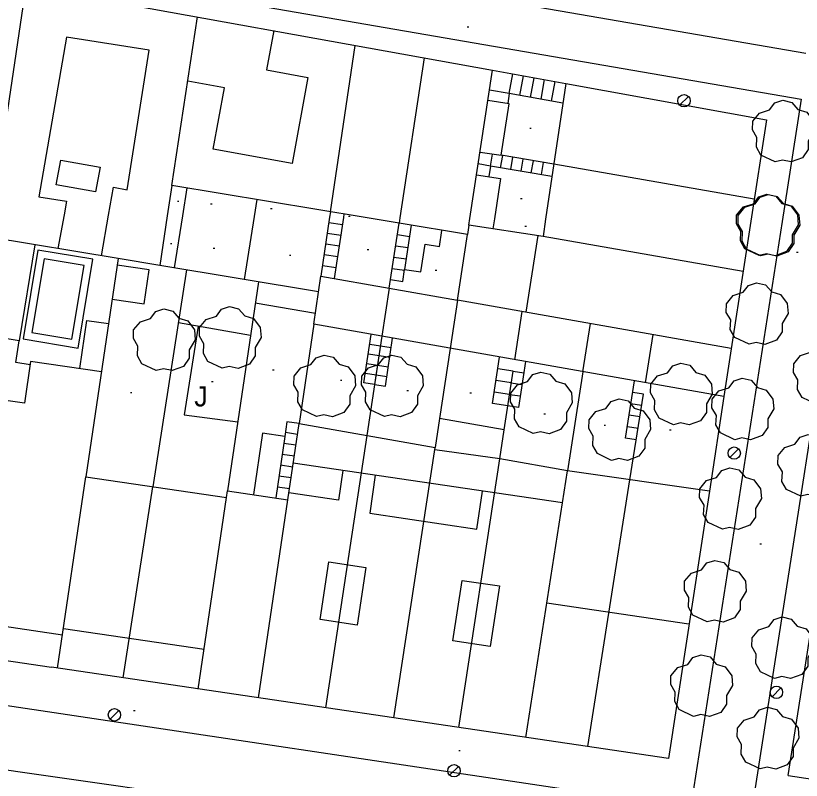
# Model space of a CAD drawing. Extents: x 431390 to 432653, y 4586754 to 4589600.
# Drawn here: x 431987.9 to 432038.9, y 4587146 to 4587195.6 of the extents above; entities that cross this region are included whole.
import ezdxf

# ---------------------------------------------------------------- set-up
doc = ezdxf.new("R2010")
doc.units = 0
for name, color, linetype in [('COM_17LS_LN', 7, 'Continuous'), ('CON_01_LN', 7, 'Continuous'), ('CON_01FI_LN', 7, 'Continuous'), ('CON_03_LN', 7, 'Continuous'), ('CON_04_LN', 7, 'Continuous'), ('CON_07_LN', 7, 'Continuous'), ('CON_14LN_LN', 7, 'Continuous'), ('CON_16_LN', 7, 'Continuous'), ('CON_23_LN', 7, 'Continuous'), ('CON_29_LN', 7, 'Continuous'), ('ENE_06_PT', 7, 'Continuous'), ('HID_11EX_LN', 7, 'Continuous'), ('HID_11IN_LN', 7, 'Continuous'), ('ORO_03_PT', 7, 'Continuous'), ('TOP_15JA_TX', 7, 'Continuous'), ('VEG_03_PT', 7, 'Continuous'), ('VEG_06_LN', 7, 'Continuous')]:
    doc.layers.add(name, color=color, linetype=linetype)

msp = doc.modelspace()

# ---------------------------------------------------------------- linework, layer by layer
at = {"layer": 'COM_17LS_LN'}
for points in [[(431987.522, 4587199.068), (432038.841, 4587190.205), (432037.603, 4587182.271), (432031.666, 4587144.248), (431980.566, 4587151.892), (431980.618, 4587152.238), (431953.282, 4587155.989), (431897.468, 4587164.433), (431900.621, 4587183.589), (431910.828, 4587250.379), (431908.915, 4587250.666), (431906.855, 4587250.975), (431896.747, 4587183.627), (431893.612, 4587165.02)], [(431987.959, 4587202.036), (432039.151, 4587193.195)], [(432035.594, 4587143.752), (432042.668, 4587189.061), (432055.977, 4587186.82)], [(432023.522, 4587088.838), (432031.211, 4587140.361), (432028.644, 4587140.733), (432001.332, 4587144.681), (431988.658, 4587146.513), (431982.216, 4587147.444)]]:
    msp.add_lwpolyline(points, dxfattribs=at)
at = {"layer": 'CON_01_LN'}
for points in [[(431984.788, 4587172.063), (431986.384, 4587182.764), (431988.59, 4587197.55), (432018.832, 4587192.088)], [(432023.578, 4587191.23), (432036.59, 4587188.88), (432035.578, 4587182.291), (432033.833, 4587170.926)], [(432037.99, 4587146.36), (432043.623, 4587182.213), (432044.477, 4587187.648)], [(431984.788, 4587172.063), (431982.178, 4587154.562), (431990.23, 4587153.37)], [(432032.892, 4587164.796), (432030.23, 4587147.46), (431990.23, 4587153.37)], [(432037.99, 4587146.36), (432045.032, 4587145.303)]]:
    msp.add_lwpolyline(points, dxfattribs=at)
at = {"layer": 'CON_01FI_LN'}
for points in [[(432023.578, 4587191.23), (432022.271, 4587182.419), (432022.107, 4587181.314), (432017.299, 4587182.029), (432017.366, 4587182.466), (432018.832, 4587192.088)], [(432033.833, 4587170.926), (432007.242, 4587175.611), (432007.704, 4587178.741), (432016.56, 4587177.18), (432017.208, 4587181.427), (432012.772, 4587182.165), (432010.565, 4587182.531), (431998.038, 4587184.614), (431997.741, 4587182.655), (431997.25, 4587179.422), (431994.546, 4587179.87), (431992.459, 4587165.716), (432001.581, 4587164.371), (432001.647, 4587164.817), (432005.562, 4587164.24), (432006.291, 4587169.175), (432015.104, 4587167.623)], [(432032.892, 4587164.796), (432023.685, 4587166.112), (432019.294, 4587166.885), (432019.58, 4587168.768), (432015.391, 4587169.505), (432015.104, 4587167.623)]]:
    msp.add_lwpolyline(points, dxfattribs=at)
at = {"layer": 'CON_03_LN'}
for points in [[(431998.038, 4587184.614), (431999.696, 4587195.544)], [(432008.319, 4587182.904), (432009.914, 4587193.699)], [(432014.398, 4587192.889), (432012.824, 4587182.51), (432012.772, 4587182.165)], [(432035.797, 4587183.715), (432022.801, 4587185.993)], [(432017.299, 4587182.029), (432017.208, 4587181.427)], [(431994.546, 4587179.87), (431986.159, 4587181.258)], [(432035.078, 4587179.037), (432022.107, 4587181.314)], [(432012.134, 4587177.96), (432011.659, 4587174.833)], [(432034.313, 4587174.05), (432016.56, 4587177.18), (432016.084, 4587174.053)], [(432020.272, 4587173.315), (432020.748, 4587176.442)], [(432024.687, 4587172.537), (432025.174, 4587175.661)], [(432029.222, 4587174.948), (432028.73, 4587171.825)], [(432010.684, 4587168.401), (432008.006, 4587150.744)], [(432012.433, 4587150.09), (432015.104, 4587167.623)], [(432020.99, 4587148.825), (432023.685, 4587166.112)], [(431990.629, 4587153.311), (431992.459, 4587165.716)], [(432025.01, 4587148.231), (432027.738, 4587165.533)], [(431999.747, 4587151.964), (432001.581, 4587164.371)], [(432003.662, 4587151.385), (432005.562, 4587164.24)]]:
    msp.add_lwpolyline(points, dxfattribs=at)
at = {"layer": 'CON_04_LN'}
for points in [[(432004.638, 4587194.652), (432004.178, 4587192.106), (432006.845, 4587191.624), (432005.835, 4587186.034), (432000.72, 4587186.958), (432001.44, 4587190.946), (431999.064, 4587191.375)], [(431993.465, 4587180.049), (431993.931, 4587182.692), (431994.25, 4587184.5), (431995.13, 4587184.34), (431996.56, 4587193.38), (431991.2, 4587194.24), (431989.41, 4587183.87), (431991.2, 4587183.59), (431991.041, 4587182.719), (431990.64, 4587180.517)], [(431990.83, 4587186.26), (431993.382, 4587185.8), (431993.093, 4587184.197), (431990.541, 4587184.657), (431990.83, 4587186.26)], [(432021.761, 4587181.365), (432020.981, 4587176.401)], [(431989.155, 4587180.762), (431988.126, 4587174.546), (431985.23, 4587175.025)], [(431992.068, 4587172.737), (431992.529, 4587175.861), (431993.925, 4587175.655)], [(431988.847, 4587172.989), (431987.917, 4587173.126), (431988.126, 4587174.546)], [(431993.464, 4587172.531), (431988.879, 4587173.207), (431988.478, 4587170.488), (431986.799, 4587170.736), (431984.686, 4587156.406), (431990.949, 4587155.482)], [(432019.294, 4587166.885), (432015.08, 4587167.465)], [(432016.643, 4587149.467), (432019.294, 4587166.885)], [(432023.361, 4587164.032), (432005.912, 4587166.61)], [(432009.129, 4587166.135), (432008.844, 4587164.204), (432005.627, 4587164.679)], [(432011.227, 4587165.825), (432010.863, 4587163.362), (432017.804, 4587162.337), (432018.168, 4587164.799)], [(431994.888, 4587152.682), (431996.812, 4587165.074)], [(432010.052, 4587156.113), (432007.644, 4587156.479), (432008.21, 4587160.214), (432010.619, 4587159.849), (432010.052, 4587156.113)], [(432018.675, 4587154.729), (432016.264, 4587155.096), (432016.86, 4587159.01), (432019.271, 4587158.643), (432018.675, 4587154.729)], [(432000.124, 4587154.516), (431991.005, 4587155.861)]]:
    msp.add_lwpolyline(points, dxfattribs=at)
at = {"layer": 'CON_07_LN'}
for points in [[(432018.022, 4587186.771), (432019.398, 4587186.568), (432019.907, 4587189.911), (432018.532, 4587190.121)], [(432017.799, 4587185.311), (432019.353, 4587185.074), (432018.954, 4587182.451), (432018.854, 4587181.798)], [(432013.561, 4587182.034), (432013.125, 4587179.165), (432014.18, 4587179.005), (432014.452, 4587180.802), (432015.388, 4587180.66), (432015.546, 4587181.703)], [(431994.159, 4587177.246), (431996.232, 4587176.94), (431996.557, 4587179.141), (431994.484, 4587179.447)], [(432003.447, 4587176.999), (432007.35, 4587176.344)], [(431998.465, 4587175.718), (432003.138, 4587174.91)], [(432005.36, 4587168.343), (432003.919, 4587168.556), (432003.33, 4587164.569)], [(432005.36, 4587168.343), (432004.771, 4587164.357)]]:
    msp.add_lwpolyline(points, dxfattribs=at)
at = {"layer": 'CON_14LN_LN'}
for points in [[(432007.553, 4587177.717), (431997.25, 4587179.422)], [(432003.648, 4587178.363), (432001.647, 4587164.817)]]:
    msp.add_lwpolyline(points, dxfattribs=at)
at = {"layer": 'CON_16_LN'}
for points in [[(432018.832, 4587192.088), (432023.578, 4587191.23)], [(431998.209, 4587179.263), (431998.741, 4587182.645), (431999.025, 4587184.45)], [(432003.551, 4587183.697), (432003.378, 4587182.601), (432002.734, 4587178.514)], [(432008.319, 4587182.904), (432008.267, 4587182.554), (432007.704, 4587178.741)], [(432012.134, 4587177.96), (432012.772, 4587182.165)], [(431998.995, 4587179.133), (431996.812, 4587165.074)], [(432007.242, 4587175.611), (432006.291, 4587169.175)], [(432011.659, 4587174.833), (432010.684, 4587168.401)], [(432016.084, 4587174.053), (432015.391, 4587169.505)], [(432019.58, 4587168.768), (432020.158, 4587172.566)], [(432024.687, 4587172.537), (432023.685, 4587166.112)], [(432027.738, 4587165.533), (432028.613, 4587171.084)], [(432033.833, 4587170.926), (432032.892, 4587164.796)]]:
    msp.add_lwpolyline(points, dxfattribs=at)
at = {"layer": 'CON_23_LN'}
for points in [[(432019.916, 4587190.571), (432020.147, 4587191.85)], [(432020.602, 4587190.447), (432020.833, 4587191.726)], [(432021.288, 4587190.323), (432021.519, 4587191.602)], [(432021.974, 4587190.199), (432022.205, 4587191.478)], [(432022.66, 4587190.075), (432022.891, 4587191.354)], [(432019.916, 4587190.571), (432018.636, 4587190.802)], [(432019.916, 4587190.571), (432019.817, 4587189.925)], [(432023.387, 4587189.944), (432019.916, 4587190.571)], [(432018.694, 4587185.875), (432018.825, 4587186.653)], [(432019.356, 4587185.763), (432019.489, 4587186.552)], [(432022.801, 4587185.993), (432019.38, 4587186.571)], [(432020.018, 4587185.651), (432020.152, 4587186.44)], [(432020.681, 4587185.539), (432020.814, 4587186.329)], [(432021.343, 4587185.428), (432021.476, 4587186.217)], [(432018.694, 4587185.875), (432017.906, 4587186.008)], [(432018.694, 4587185.875), (432018.579, 4587185.192)], [(432022.684, 4587185.201), (432018.694, 4587185.875)], [(432022.005, 4587185.316), (432022.138, 4587186.105)], [(432008.59, 4587178.585), (432009.176, 4587182.545), (432009.207, 4587182.757)], [(432008.216, 4587182.211), (432009.107, 4587182.08)], [(432008.114, 4587181.517), (432009.004, 4587181.386)], [(432012.661, 4587181.434), (432013.452, 4587181.314)], [(432008.011, 4587180.823), (432008.902, 4587180.692)], [(432012.55, 4587180.703), (432013.341, 4587180.583)], [(432007.909, 4587180.129), (432008.799, 4587179.998)], [(432012.439, 4587179.971), (432013.229, 4587179.851)], [(432007.806, 4587179.435), (432008.696, 4587179.304)], [(432012.217, 4587178.509), (432013.008, 4587178.389), (432013.126, 4587179.165)], [(432012.328, 4587179.24), (432013.119, 4587179.12)], [(432011.186, 4587171.715), (432010.494, 4587171.82), (432010.969, 4587174.954)], [(432011.659, 4587174.833), (432011.186, 4587171.715)], [(432011.186, 4587171.715), (432011.878, 4587171.61), (432012.348, 4587174.711)], [(432010.872, 4587174.314), (432011.564, 4587174.209), (432012.256, 4587174.104)], [(432010.778, 4587173.691), (432011.47, 4587173.586), (432012.162, 4587173.481)], [(432020.962, 4587173.194), (432020.508, 4587170.214), (432019.816, 4587170.319), (432018.827, 4587170.469), (432019.287, 4587173.489)], [(432010.683, 4587173.067), (432011.375, 4587172.962), (432012.067, 4587172.857)], [(432010.589, 4587172.444), (432011.281, 4587172.339), (432011.973, 4587172.234)], [(432020.158, 4587172.566), (432019.169, 4587172.716)], [(432020.158, 4587172.566), (432020.85, 4587172.461)], [(432020.044, 4587171.817), (432019.055, 4587171.967)], [(432028.146, 4587168.121), (432027.455, 4587168.23), (432028.041, 4587171.946)], [(432020.044, 4587171.817), (432020.736, 4587171.712)], [(432019.93, 4587171.068), (432018.941, 4587171.218)], [(432019.93, 4587171.068), (432020.622, 4587170.963)], [(432028.613, 4587171.084), (432027.922, 4587171.193)], [(432028.496, 4587170.343), (432027.805, 4587170.452)], [(432028.38, 4587169.603), (432027.689, 4587169.712)], [(432006.291, 4587169.175), (432005.5, 4587169.292), (432005.36, 4587168.343)], [(432028.263, 4587168.862), (432027.572, 4587168.971)], [(432006.187, 4587168.47), (432005.396, 4587168.587)], [(432006.083, 4587167.765), (432005.292, 4587167.882)], [(432005.979, 4587167.06), (432005.188, 4587167.177)], [(432005.874, 4587166.355), (432005.084, 4587166.472)], [(432005.77, 4587165.65), (432004.979, 4587165.767)], [(432005.666, 4587164.945), (432004.875, 4587165.062)]]:
    msp.add_lwpolyline(points, dxfattribs=at)
at = {"layer": 'CON_29_LN'}
msp.add_lwpolyline([(432031.566, 4587156.163), (432022.347, 4587157.532)], dxfattribs=at)
at = {"layer": 'ENE_06_PT'}
for p, q in [((432031.529, 4587190.393), (432030.963, 4587189.827)), ((432034.782, 4587167.542), (432034.216, 4587166.976)), ((432037.522, 4587152.032), (432036.956, 4587151.466)), ((431994.592, 4587150.572), (431994.026, 4587150.006)), ((432016.614, 4587146.943), (432016.048, 4587146.377))]:
    msp.add_line(p, q, dxfattribs=at)
for centre in [(432031.246, 4587190.11), (432034.499, 4587167.259), (432037.239, 4587151.749), (431994.309, 4587150.289), (432016.331, 4587146.66)]:
    msp.add_circle(centre, 0.4, dxfattribs=at)
at = {"layer": 'HID_11EX_LN'}
msp.add_lwpolyline([(431988.385, 4587174.662), (431991.963, 4587174.069), (431992.917, 4587179.836), (431989.339, 4587180.428), (431988.385, 4587174.662)], dxfattribs=at)
at = {"layer": 'HID_11IN_LN'}
msp.add_lwpolyline([(431988.96, 4587175.073), (431991.551, 4587174.644), (431992.342, 4587179.424), (431989.751, 4587179.853), (431988.96, 4587175.073)], dxfattribs=at)
at = {"layer": 'ORO_03_PT'}
for p, q in [((432017.183, 4587194.905), (432017.283, 4587194.905)), ((432021.24, 4587188.34), (432021.34, 4587188.34)), ((431998.39, 4587183.59), (431998.49, 4587183.59)), ((432020.65, 4587183.77), (432020.75, 4587183.77)), ((432000.54, 4587183.43), (432000.64, 4587183.43)), ((432004.43, 4587183.11), (432004.53, 4587183.11)), ((432009.5, 4587182.62), (432009.6, 4587182.62)), ((432020.93, 4587181.97), (432021.03, 4587181.97)), ((431997.94, 4587180.85), (431998.04, 4587180.85)), ((432000.72, 4587180.54), (432000.82, 4587180.54)), ((432005.66, 4587180.1), (432005.76, 4587180.1)), ((432010.71, 4587180.47), (432010.81, 4587180.47)), ((432038.55, 4587180.29), (432038.65, 4587180.29)), ((432015.12, 4587179.13), (432015.22, 4587179.13)), ((432004.56, 4587172.66), (432004.66, 4587172.66)), ((432000.61, 4587171.91), (432000.71, 4587171.91)), ((432008.96, 4587172), (432009.06, 4587172)), ((431995.35, 4587171.18), (431995.45, 4587171.18)), ((432013.28, 4587171.32), (432013.38, 4587171.32)), ((432017.36, 4587171.17), (432017.46, 4587171.17)), ((432022.16, 4587169.8), (432022.26, 4587169.8)), ((432026.06, 4587169.07), (432026.16, 4587169.07)), ((432030.31, 4587168.77), (432030.41, 4587168.77)), ((432036.173, 4587161.387), (432036.273, 4587161.387)), ((431995.55, 4587150.57), (431995.65, 4587150.57)), ((432016.64, 4587147.98), (432016.74, 4587147.98))]:
    msp.add_line(p, q, dxfattribs=at)
at = {"layer": 'VEG_03_PT'}
for points in [[(432037.164, 4587186.151), (432036.237, 4587186.586), (432035.949, 4587187.107), (432035.972, 4587187.721), (432035.69, 4587188.213), (432035.698, 4587188.776), (432036.139, 4587189.311), (432036.792, 4587189.515), (432037.127, 4587189.966), (432037.653, 4587190.136), (432038.233, 4587190.003), (432038.633, 4587189.537), (432039.207, 4587189.367), (432039.641, 4587188.784), (432039.69, 4587188.142), (432039.307, 4587187.495), (432039.307, 4587186.945), (432038.935, 4587186.411), (432038.196, 4587186.136), (432037.631, 4587186.264), (432037.164, 4587186.151)], [(432036.125, 4587180.068), (432035.198, 4587180.503), (432034.91, 4587181.024), (432034.933, 4587181.638), (432034.651, 4587182.13), (432034.659, 4587182.693), (432035.1, 4587183.228), (432035.753, 4587183.432), (432036.088, 4587183.883), (432036.614, 4587184.053), (432037.194, 4587183.92), (432037.594, 4587183.454), (432038.168, 4587183.284), (432038.602, 4587182.701), (432038.651, 4587182.059), (432038.268, 4587181.412), (432038.268, 4587180.862), (432037.896, 4587180.328), (432037.157, 4587180.053), (432036.592, 4587180.181), (432036.125, 4587180.068)], [(432036.224, 4587180.051), (432035.297, 4587180.486), (432035.009, 4587181.007), (432035.032, 4587181.621), (432034.75, 4587182.113), (432034.758, 4587182.676), (432035.199, 4587183.211), (432035.852, 4587183.415), (432036.187, 4587183.866), (432036.713, 4587184.036), (432037.293, 4587183.903), (432037.693, 4587183.437), (432038.267, 4587183.267), (432038.701, 4587182.684), (432038.75, 4587182.042), (432038.367, 4587181.395), (432038.367, 4587180.845), (432037.995, 4587180.311), (432037.256, 4587180.036), (432036.691, 4587180.164), (432036.224, 4587180.051)], [(432035.464, 4587174.321), (432034.537, 4587174.756), (432034.249, 4587175.277), (432034.272, 4587175.891), (432033.99, 4587176.383), (432033.998, 4587176.946), (432034.439, 4587177.481), (432035.092, 4587177.685), (432035.427, 4587178.136), (432035.953, 4587178.306), (432036.533, 4587178.173), (432036.933, 4587177.707), (432037.507, 4587177.537), (432037.941, 4587176.954), (432037.99, 4587176.312), (432037.607, 4587175.665), (432037.607, 4587175.115), (432037.235, 4587174.581), (432036.496, 4587174.306), (432035.931, 4587174.434), (432035.464, 4587174.321)], [(431997.024, 4587172.621), (431996.097, 4587173.056), (431995.809, 4587173.577), (431995.832, 4587174.191), (431995.55, 4587174.683), (431995.558, 4587175.246), (431995.999, 4587175.781), (431996.652, 4587175.985), (431996.987, 4587176.436), (431997.513, 4587176.606), (431998.093, 4587176.473), (431998.493, 4587176.007), (431999.067, 4587175.837), (431999.501, 4587175.254), (431999.55, 4587174.612), (431999.167, 4587173.965), (431999.167, 4587173.415), (431998.795, 4587172.881), (431998.056, 4587172.606), (431997.491, 4587172.734), (431997.024, 4587172.621)], [(432001.294, 4587172.771), (432000.367, 4587173.206), (432000.079, 4587173.727), (432000.102, 4587174.341), (431999.82, 4587174.833), (431999.828, 4587175.396), (432000.269, 4587175.931), (432000.922, 4587176.135), (432001.257, 4587176.586), (432001.783, 4587176.756), (432002.363, 4587176.623), (432002.763, 4587176.157), (432003.337, 4587175.987), (432003.771, 4587175.404), (432003.82, 4587174.762), (432003.437, 4587174.115), (432003.437, 4587173.565), (432003.065, 4587173.031), (432002.326, 4587172.756), (432001.761, 4587172.884), (432001.294, 4587172.771)], [(432039.824, 4587170.431), (432038.897, 4587170.866), (432038.609, 4587171.387), (432038.632, 4587172.001), (432038.35, 4587172.493), (432038.358, 4587173.056), (432038.799, 4587173.591), (432039.452, 4587173.795), (432039.787, 4587174.246), (432040.313, 4587174.416), (432040.893, 4587174.283), (432041.293, 4587173.817), (432041.867, 4587173.647), (432042.301, 4587173.064), (432042.35, 4587172.422), (432041.967, 4587171.775), (432041.967, 4587171.225), (432041.595, 4587170.691), (432040.856, 4587170.416), (432040.291, 4587170.544), (432039.824, 4587170.431)], [(432007.424, 4587169.631), (432006.497, 4587170.066), (432006.209, 4587170.587), (432006.232, 4587171.201), (432005.95, 4587171.693), (432005.958, 4587172.256), (432006.399, 4587172.791), (432007.052, 4587172.995), (432007.387, 4587173.446), (432007.913, 4587173.616), (432008.493, 4587173.483), (432008.893, 4587173.017), (432009.467, 4587172.847), (432009.901, 4587172.264), (432009.95, 4587171.622), (432009.567, 4587170.975), (432009.567, 4587170.425), (432009.195, 4587169.891), (432008.456, 4587169.616), (432007.891, 4587169.744), (432007.424, 4587169.631)], [(432011.814, 4587169.631), (432010.887, 4587170.066), (432010.599, 4587170.587), (432010.622, 4587171.201), (432010.34, 4587171.693), (432010.348, 4587172.256), (432010.789, 4587172.791), (432011.442, 4587172.995), (432011.777, 4587173.446), (432012.303, 4587173.616), (432012.883, 4587173.483), (432013.283, 4587173.017), (432013.857, 4587172.847), (432014.291, 4587172.264), (432014.34, 4587171.622), (432013.957, 4587170.975), (432013.957, 4587170.425), (432013.585, 4587169.891), (432012.846, 4587169.616), (432012.281, 4587169.744), (432011.814, 4587169.631)], [(432030.554, 4587169.101), (432029.627, 4587169.536), (432029.339, 4587170.057), (432029.362, 4587170.671), (432029.08, 4587171.163), (432029.088, 4587171.726), (432029.529, 4587172.261), (432030.182, 4587172.465), (432030.517, 4587172.916), (432031.043, 4587173.086), (432031.623, 4587172.953), (432032.023, 4587172.487), (432032.597, 4587172.317), (432033.031, 4587171.734), (432033.08, 4587171.092), (432032.697, 4587170.445), (432032.697, 4587169.895), (432032.325, 4587169.361), (432031.586, 4587169.086), (432031.021, 4587169.214), (432030.554, 4587169.101)], [(432021.474, 4587168.531), (432020.547, 4587168.966), (432020.259, 4587169.487), (432020.282, 4587170.101), (432020, 4587170.593), (432020.008, 4587171.156), (432020.449, 4587171.691), (432021.102, 4587171.895), (432021.437, 4587172.346), (432021.963, 4587172.516), (432022.543, 4587172.383), (432022.943, 4587171.917), (432023.517, 4587171.747), (432023.951, 4587171.164), (432024, 4587170.522), (432023.617, 4587169.875), (432023.617, 4587169.325), (432023.245, 4587168.791), (432022.506, 4587168.516), (432021.941, 4587168.644), (432021.474, 4587168.531)], [(432034.534, 4587168.131), (432033.607, 4587168.566), (432033.319, 4587169.087), (432033.342, 4587169.701), (432033.06, 4587170.193), (432033.068, 4587170.756), (432033.509, 4587171.291), (432034.162, 4587171.495), (432034.497, 4587171.946), (432035.023, 4587172.116), (432035.603, 4587171.983), (432036.003, 4587171.517), (432036.577, 4587171.347), (432037.011, 4587170.764), (432037.06, 4587170.122), (432036.677, 4587169.475), (432036.677, 4587168.925), (432036.305, 4587168.391), (432035.566, 4587168.116), (432035.001, 4587168.244), (432034.534, 4587168.131)], [(432026.554, 4587166.791), (432025.627, 4587167.226), (432025.339, 4587167.747), (432025.362, 4587168.361), (432025.08, 4587168.853), (432025.088, 4587169.416), (432025.529, 4587169.951), (432026.182, 4587170.155), (432026.517, 4587170.606), (432027.043, 4587170.776), (432027.623, 4587170.643), (432028.023, 4587170.177), (432028.597, 4587170.007), (432029.031, 4587169.424), (432029.08, 4587168.782), (432028.697, 4587168.135), (432028.697, 4587167.585), (432028.325, 4587167.051), (432027.586, 4587166.776), (432027.021, 4587166.904), (432026.554, 4587166.791)], [(432038.814, 4587164.471), (432037.887, 4587164.906), (432037.599, 4587165.427), (432037.622, 4587166.041), (432037.34, 4587166.533), (432037.348, 4587167.096), (432037.789, 4587167.631), (432038.442, 4587167.835), (432038.777, 4587168.286), (432039.303, 4587168.456), (432039.883, 4587168.323), (432040.283, 4587167.857), (432040.857, 4587167.687), (432041.291, 4587167.104), (432041.34, 4587166.462), (432040.957, 4587165.815), (432040.957, 4587165.265), (432040.585, 4587164.731), (432039.846, 4587164.456), (432039.281, 4587164.584), (432038.814, 4587164.471)], [(432033.734, 4587162.321), (432032.807, 4587162.756), (432032.519, 4587163.277), (432032.542, 4587163.891), (432032.26, 4587164.383), (432032.268, 4587164.946), (432032.709, 4587165.481), (432033.362, 4587165.685), (432033.697, 4587166.136), (432034.223, 4587166.306), (432034.803, 4587166.173), (432035.203, 4587165.707), (432035.777, 4587165.537), (432036.211, 4587164.954), (432036.26, 4587164.312), (432035.877, 4587163.665), (432035.877, 4587163.115), (432035.505, 4587162.581), (432034.766, 4587162.306), (432034.201, 4587162.434), (432033.734, 4587162.321)], [(432032.754, 4587156.321), (432031.827, 4587156.756), (432031.539, 4587157.277), (432031.562, 4587157.891), (432031.28, 4587158.383), (432031.288, 4587158.946), (432031.729, 4587159.481), (432032.382, 4587159.685), (432032.717, 4587160.136), (432033.243, 4587160.306), (432033.823, 4587160.173), (432034.223, 4587159.707), (432034.797, 4587159.537), (432035.231, 4587158.954), (432035.28, 4587158.312), (432034.897, 4587157.665), (432034.897, 4587157.115), (432034.525, 4587156.581), (432033.786, 4587156.306), (432033.221, 4587156.434), (432032.754, 4587156.321)], [(432037.124, 4587152.651), (432036.197, 4587153.086), (432035.909, 4587153.607), (432035.932, 4587154.221), (432035.65, 4587154.713), (432035.658, 4587155.276), (432036.099, 4587155.811), (432036.752, 4587156.015), (432037.087, 4587156.466), (432037.613, 4587156.636), (432038.193, 4587156.503), (432038.593, 4587156.037), (432039.167, 4587155.867), (432039.601, 4587155.284), (432039.65, 4587154.642), (432039.267, 4587153.995), (432039.267, 4587153.445), (432038.895, 4587152.911), (432038.156, 4587152.636), (432037.591, 4587152.764), (432037.124, 4587152.651)], [(432031.864, 4587150.191), (432030.937, 4587150.626), (432030.649, 4587151.147), (432030.672, 4587151.761), (432030.39, 4587152.253), (432030.398, 4587152.816), (432030.839, 4587153.351), (432031.492, 4587153.555), (432031.827, 4587154.006), (432032.353, 4587154.176), (432032.933, 4587154.043), (432033.333, 4587153.577), (432033.907, 4587153.407), (432034.341, 4587152.824), (432034.39, 4587152.182), (432034.007, 4587151.535), (432034.007, 4587150.985), (432033.635, 4587150.451), (432032.896, 4587150.176), (432032.331, 4587150.304), (432031.864, 4587150.191)], [(432036.174, 4587146.791), (432035.247, 4587147.226), (432034.959, 4587147.747), (432034.982, 4587148.361), (432034.7, 4587148.853), (432034.708, 4587149.416), (432035.149, 4587149.951), (432035.802, 4587150.155), (432036.137, 4587150.606), (432036.663, 4587150.776), (432037.243, 4587150.643), (432037.643, 4587150.177), (432038.217, 4587150.007), (432038.651, 4587149.424), (432038.7, 4587148.782), (432038.317, 4587148.135), (432038.317, 4587147.585), (432037.945, 4587147.051), (432037.206, 4587146.776), (432036.641, 4587146.904), (432036.174, 4587146.791)]]:
    msp.add_lwpolyline(points, dxfattribs=at)
at = {"layer": 'VEG_06_LN'}
msp.add_lwpolyline([(431999.741, 4587175.497), (431998.84, 4587169.74), (432002.306, 4587169.281)], dxfattribs=at)

# ---------------------------------------------------------------- texts
at = {"layer": 'TOP_15JA_TX'}
msp.add_text('J', height=1.3, dxfattribs=at).set_placement((431999.49, 4587170.285))

doc.saveas('drawing.dxf')
